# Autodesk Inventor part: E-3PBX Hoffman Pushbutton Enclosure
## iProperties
Title: E-3PBX Hoffman Pushbutton Enclosure
Author: S Dotson
Shininess: 0.0
Length Units: 11272
Angle Units: 11286
Time Units: 11279
Mass Units: 11290
Length Display Precision: 4
Angle Display Precision: 2
Compacted: True
PropertySet Name: _Private Model Information
Created: 2001-11
Part Number: E-3PBX
Material: Steel, Mild
Document SubType Name: Modeling
Designer: S Dotson
Control State: 0
Master: False
Checked Out: False
PropertySet Name: Design Tracking Control
Density: 7.86
Volumn: 94.01930371226516
Area: 815.033447019008
PropertySet Name: Model Information
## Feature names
1. Extrusion3
2. Fillet1
3. Shell1
4. Extrusion4
5. Extrusion6
6. Rectangular Pattern1
7. Extrusion7
8. Extrusion9
9. Extrusion10
10. Fillet4
11. Rectangular Pattern2
12. Mirror1
13. Extrusion11
14. Fillet5
15. Extrusion12
16. Rectangular Pattern3
